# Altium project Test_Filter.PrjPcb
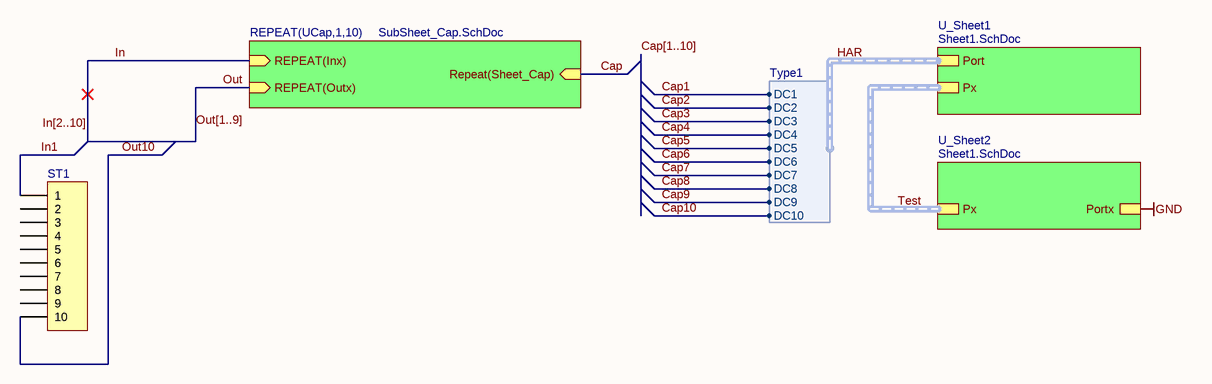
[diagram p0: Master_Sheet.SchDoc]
Address_1: Forschungszentrum Jülich; Address_2: ZEA-2; Address_3: 52425 Jülich; Address_4: www.fz-juelich.de; CreationDate: 16.12.2019; Designer: W.Glaas; EMail: w.glaas@fz-juelich.de; Institut: ZEA-2; PCBSerialnumber: Wxxx; Project: Please enter project; Project_Title: Please enter project title; ProjektTitle: Projekt Title; RevNumber: 0; WNummer: W2xx
3 sheets, 25 parts. Net scope: hierarchical (ports join the sheet entries above them; power ports are global).
Board file: Test_Filter.PCBDOC
Sheets:
  Master_Sheet.SchDoc
    UCap1 = SubSheet_Cap.SchDoc
    UCap2 = SubSheet_Cap.SchDoc
    UCap3 = SubSheet_Cap.SchDoc
    UCap4 = SubSheet_Cap.SchDoc
    UCap5 = SubSheet_Cap.SchDoc
    UCap6 = SubSheet_Cap.SchDoc
    UCap7 = SubSheet_Cap.SchDoc
    UCap8 = SubSheet_Cap.SchDoc
    UCap9 = SubSheet_Cap.SchDoc
    UCap10 = SubSheet_Cap.SchDoc
    U_Sheet1 = Sheet1.SchDoc
    U_Sheet2 = Sheet1.SchDoc

## Sheet Master_Sheet.SchDoc
size A4; CompanyName: FZ-Jülich; Organization: Forschungszentrum Jülich; Address1: ZEA-2; Address3: 52425 Jülich; Address4: www.fz-juelich.de; Revision: 1; SheetNumber: 1; SheetTotal: 3; TTTestTT: Test123

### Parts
ST1  (no value)  [CON_HDR1X10]

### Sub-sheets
REPEAT(UCap,1,10) = SubSheet_Cap.SchDoc: Repeat(Sheet_Cap) (in), REPEAT(Inx) (in), REPEAT(Outx) (in)
U_Sheet1 = Sheet1.SchDoc: Port (harness Type1), Px (harness Type2)
U_Sheet2 = Sheet1.SchDoc: Portx, Px (harness Type2)

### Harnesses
Type1: DC1, DC2, DC3, DC4, DC5, DC6, DC7, DC8, DC9, DC10

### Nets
In1: ST1.1
Out10: ST1.10

Not connected (* = marked no-connect by the designer): ST1 2 3 4 5 6 7 8 9

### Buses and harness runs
bus Cap[1..10]
bus In[2..10] = Out[1..9]
harness HAR = sheet U_Sheet1/Port
harness Test = sheet U_Sheet1/Px = sheet U_Sheet2/Px

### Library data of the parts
ST1 = CON_Header 10: Header, 10-Pin; Mfr Part Number: Samtec TSW-110-07-L-S; User: W.Glaas; Validated: False

## Sheet SubSheet_Cap.SchDoc
size A4; CompanyName: FZ-Jülich; Organization: Forschungszentrum Jülich; Address1: ZEA-2; Address3: 52425 Jülich; Address4: www.fz-juelich.de; Revision: 1; SheetNumber: 2; SheetTotal: 3; TTTestTT: Test123
Used 10 times, as channels UCap1, UCap2, UCap3, UCap4, UCap5, UCap6, UCap7, UCap8, UCap9, UCap10. Parts and nets are listed once, with the designators drawn on the sheet.
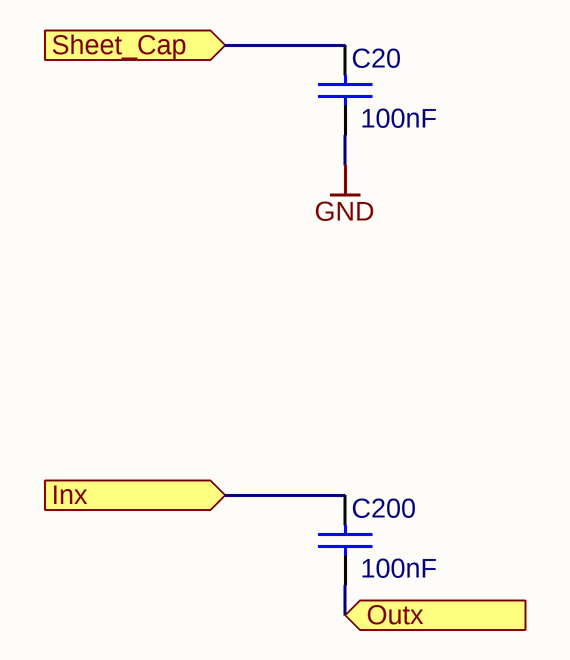
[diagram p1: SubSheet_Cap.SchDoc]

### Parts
C20  100nF  [CAPC3216X140N]
C200  100nF  [CAPC3216X140N]

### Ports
Inx (in), Outx (in), Sheet_Cap (in)

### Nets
GND: C20.2
Inx: C200.1 ; port Inx
Outx: C200.2 ; port Outx
Sheet_Cap: C20.1 ; port Sheet_Cap

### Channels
UCap1: designators end in _1; ports Inx=In1 Outx=In2 Sheet_Cap=Cap1
UCap2: designators end in _2; ports Inx=In2 Outx=In3 Sheet_Cap=Cap2
UCap3: designators end in _3; ports Inx=In3 Outx=In4 Sheet_Cap=Cap3
UCap4: designators end in _4; ports Inx=In4 Outx=In5 Sheet_Cap=Cap4
UCap5: designators end in _5; ports Inx=In5 Outx=In6 Sheet_Cap=Cap5
UCap6: designators end in _6; ports Inx=In6 Outx=In7 Sheet_Cap=Cap6
UCap7: designators end in _7; ports Inx=In7 Outx=In8 Sheet_Cap=Cap7
UCap8: designators end in _8; ports Inx=In8 Outx=In9 Sheet_Cap=Cap8
UCap9: designators end in _9; ports Inx=In9 Outx=In10 Sheet_Cap=Cap9
UCap10: designators end in _10; ports Inx=In10 Outx=Out10 Sheet_Cap=Cap10

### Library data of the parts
C20 C200 = CAP_Chip_3216: Capacitor General; Part Description: Capacitor ceramic, chip (1206); Mfr Part Number: e.g. Vishay VJ1210Y104KXCT (100nF); Type: CAP; User: W.Glaas; Validated: False

## Sheet Sheet1.SchDoc
size A4; CompanyName: FZ-Jülich; Organization: Forschungszentrum Jülich; Address1: ZEA-2; Address3: 52425 Jülich; Address4: www.fz-juelich.de; Revision: 1; SheetNumber: 1; SheetTotal: 1; TTTestTT: Test123
Used 2 times, as channels U_Sheet1, U_Sheet2. Parts and nets are listed once, with the designators drawn on the sheet.
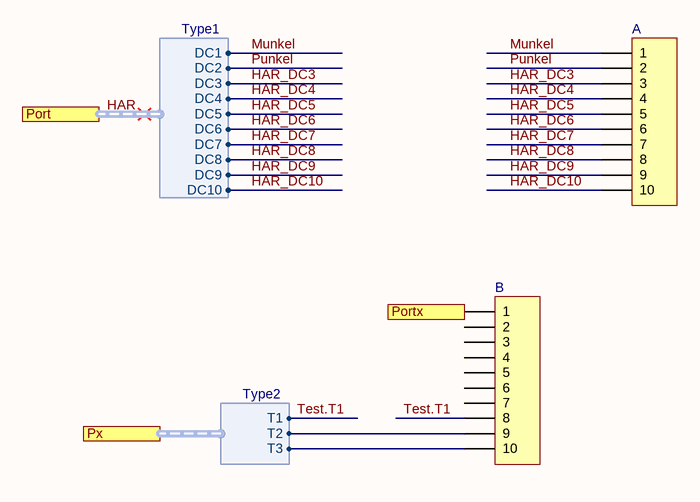
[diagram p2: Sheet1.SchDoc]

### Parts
A  (no value)  [CON_HDR1X10]
B  (no value)  [CON_HDR1X10]

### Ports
Port (harness Type1), Portx, Px (harness Type2)

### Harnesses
Type1: DC1, DC2, DC3, DC4, DC5, DC6, DC7, DC8, DC9, DC10
Type2: T1, T2, T3

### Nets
HAR_DC3: A.3 ; port Port.DC3  [project net HAR.DC3]
HAR_DC4: A.4 ; port Port.DC4  [project net HAR.DC4]
HAR_DC5: A.5 ; port Port.DC5  [project net HAR.DC5]
HAR_DC6: A.6 ; port Port.DC6  [project net HAR.DC6]
HAR_DC7: A.7 ; port Port.DC7  [project net HAR.DC7]
HAR_DC8: A.8 ; port Port.DC8  [project net HAR.DC8]
HAR_DC9: A.9 ; port Port.DC9  [project net HAR.DC9]
HAR_DC10: A.10 ; port Port.DC10  [project net HAR.DC10]
Munkel: A.1 ; port Port.DC1  [project net HAR.DC1]
Portx: B.1 ; port Portx
Punkel: A.2 ; port Port.DC2  [project net HAR.DC2]
Test.T1: B.8 ; port Px.T1
NetB_9: B.9 ; port Px.T2
NetB_10: B.10 ; port Px.T3

Not connected (* = marked no-connect by the designer): B 2 3 4 5 6 7

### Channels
U_Sheet1: designators end in _1; ports Portx=NetB_1_1
U_Sheet2: designators end in _2; ports Portx=GND

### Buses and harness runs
harness HAR = port Port

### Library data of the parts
A B = CON_Header 10: as ST1 on sheet Master_Sheet

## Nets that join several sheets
GND: UCap1 (C20_1.2), UCap2 (C20_2.2), UCap3 (C20_3.2), UCap4 (C20_4.2), UCap5 (C20_5.2), UCap6 (C20_6.2), UCap7 (C20_7.2), UCap8 (C20_8.2), UCap9 (C20_9.2), UCap10 (C20_10.2), U_Sheet2 (B_2.1)
Cap1: UCap1 (C20_1.1), U_Sheet1 (A_1.1)
Cap2: UCap2 (C20_2.1), U_Sheet1 (A_1.2)
Cap3: UCap3 (C20_3.1), U_Sheet1 (A_1.3)
Cap4: UCap4 (C20_4.1), U_Sheet1 (A_1.4)
Cap5: UCap5 (C20_5.1), U_Sheet1 (A_1.5)
Cap6: UCap6 (C20_6.1), U_Sheet1 (A_1.6)
Cap7: UCap7 (C20_7.1), U_Sheet1 (A_1.7)
Cap8: UCap8 (C20_8.1), U_Sheet1 (A_1.8)
Cap9: UCap9 (C20_9.1), U_Sheet1 (A_1.9)
Cap10: UCap10 (C20_10.1), U_Sheet1 (A_1.10)
In1: Master_Sheet (ST1.1), UCap1 (C200_1.1)
In2: UCap1 (C200_1.2), UCap2 (C200_2.1)
In3: UCap2 (C200_2.2), UCap3 (C200_3.1)
In4: UCap3 (C200_3.2), UCap4 (C200_4.1)
In5: UCap4 (C200_4.2), UCap5 (C200_5.1)
In6: UCap5 (C200_5.2), UCap6 (C200_6.1)
In7: UCap6 (C200_6.2), UCap7 (C200_7.1)
In8: UCap7 (C200_7.2), UCap8 (C200_8.1)
In9: UCap8 (C200_8.2), UCap9 (C200_9.1)
In10: UCap9 (C200_9.2), UCap10 (C200_10.1)
Out10: Master_Sheet (ST1.10), UCap10 (C200_10.2)
Test.T1: U_Sheet1 (B_1.8), U_Sheet2 (B_2.8)
Test.T2: U_Sheet1 (B_1.9), U_Sheet2 (B_2.9)
Test.T3: U_Sheet1 (B_1.10), U_Sheet2 (B_2.10)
